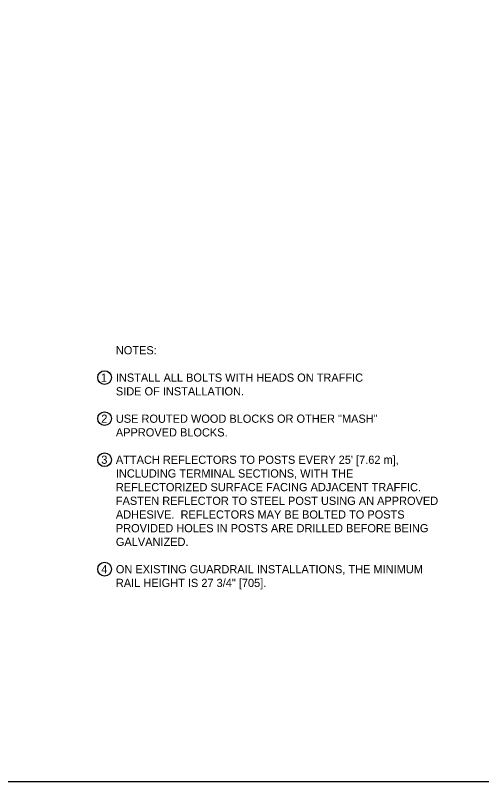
# Model space of a CAD drawing. Extents: x 49991.4 to 50021, y 49987.6 to 50011.4.
# Drawn here: x 50005.28 to 50008.69, y 49987.8 to 49993.4 of the extents above; entities that cross this region are included whole.
import ezdxf

# ---------------------------------------------------------------- set-up
doc = ezdxf.new("R2010")
doc.units = 0
doc.layers.add('Level 1', color=7, linetype='Continuous')
doc.layers.add('Level 2', color=7, linetype='Continuous')

msp = doc.modelspace()

# ---------------------------------------------------------------- linework, layer by layer
at = {"layer": 'Level 1'}
msp.add_lwpolyline([(49999.3835, 49998.9992), (50016.7501, 49998.9992), (50016.7501, 49987.7988), (49999.3835, 49987.7988)], close=True, dxfattribs=at)
at = {"layer": 'Level 2'}
for centre in [(50005.9354, 49990.7517), (50005.9354, 49990.4517), (50005.9354, 49990.1517), (50005.9354, 49989.3517)]:
    msp.add_circle(centre, 0.05, dxfattribs=at)

# ---------------------------------------------------------------- texts
for s, p in [('NOTES:', (50006.018, 49990.9214)), ('1', (50005.9086, 49990.7214)), ('INSTALL ALL BOLTS WITH HEADS ON TRAFFIC', (50006.018, 49990.7214)), ('SIDE OF INSTALLATION.', (50006.018, 49990.6214)), ('2', (50005.9113, 49990.4216)), ('USE ROUTED WOOD BLOCKS OR OTHER "MASH"', (50006.018, 49990.4214)), ('APPROVED BLOCKS.', (50006.018, 49990.3214)), ('3', (50005.9114, 49990.1216)), ("ATTACH REFLECTORS TO POSTS EVERY 25' [7.62 m], ", (50006.018, 49990.1214)), ('INCLUDING TERMINAL SECTIONS, WITH THE ', (50006.018, 49990.0214)), ('REFLECTORIZED SURFACE FACING ADJACENT TRAFFIC.', (50006.018, 49989.9214)), ('FASTEN REFLECTOR TO STEEL POST USING AN APPROVED ', (50006.018, 49989.8214)), ('ADHESIVE.  REFLECTORS MAY BE BOLTED TO POSTS ', (50006.018, 49989.7214)), ('PROVIDED HOLES IN POSTS ARE DRILLED BEFORE BEING ', (50006.018, 49989.6214)), ('GALVANIZED.', (50006.018, 49989.5214)), ('4', (50005.9114, 49989.3217)), ('ON EXISTING GUARDRAIL INSTALLATIONS, THE MINIMUM', (50006.018, 49989.3214)), ('RAIL HEIGHT IS 27 3/4" [705]. ', (50006.018, 49989.2214))]:
    msp.add_text(s, height=0.06, dxfattribs=at).set_placement(p)

doc.saveas('drawing.dxf')
